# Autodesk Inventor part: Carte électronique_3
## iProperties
Created: 2010-07
Part Number: Carte électronique_3
Document SubType Name: Modeling
Designer: eric
Density: 1 g/cm^3
Author: eric
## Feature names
1. Base1
